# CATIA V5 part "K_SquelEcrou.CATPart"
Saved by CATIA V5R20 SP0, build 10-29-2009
Part number: Squelette_ecrou
Publications: "Plan_écrou", "Droite_écrou", "Point_centre_écrou", "Axe_écrou", "Axe_pivot_écrou_1", "Axe_pivot_écrou_2"
Bounding box of the stored display mesh (mm): x -210 to -170, y -92.303 to 50, z -50 to 50
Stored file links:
  G:\Khaled_CFAO_2011\ST2M\ST2M_GR2\jcoetard\Khaled\CAD_CATIA\K_SquelEcrou.CATPart
  G:\Khaled_CFAO_2011\ST2M\ST2M_GR2\jcoetard\jcoetard\Maquette_jcoetard\Squelette General.CATPart
  G:\Khaled_CFAO_2011\ST2M\ST2M_GR2\jcoetard\Khaled\CAD_CATIA\K_Squelette.CATProduct
  G:\Khaled_CFAO_2011\ST2M\ST2M_GR2\jcoetard\jcoetard\Maquette_jcoetard\Squelette_tige.CATPart
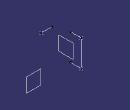
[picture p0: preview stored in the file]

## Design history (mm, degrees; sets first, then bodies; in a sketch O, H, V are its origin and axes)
External parameters (linked from other documents)
  External.Longueur_bielle_motrice = 90 mm
Set1
  Point1: linked copy from another document
  Point2 "Point.12": linked copy from another document
  Plane1 "Plan_Ref": linked copy from another document
Set2 "Set géométrique"
  Plane2 "Plan_écrou": type Offset, RefPlane yz-plane, Offset -170 {= -2*External.Longueur_bielle_motrice+10mm}
  Line1 "Droite_écrou": type PtPt, FirstPoint Point1, SecondPoint Point2
  Point3 "Point_centre_écrou": type OnPlane, Support Plane2, H -92.303, V 0, Direction (0, 1, 0)
  Line2 "Axe_écrou": type Normal, RefPoint Point3, RefSkin Plane2, Start 0, End 40
  Line3 "Axe_pivot_écrou_1": type Normal, RefPoint Point1, RefSkin Plane1, Start 0, End 40
  Line4 "Axe_pivot_écrou_2": type Normal, RefPoint Point2, RefSkin Plane1, Start 0, End 40
Body1 (main body)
